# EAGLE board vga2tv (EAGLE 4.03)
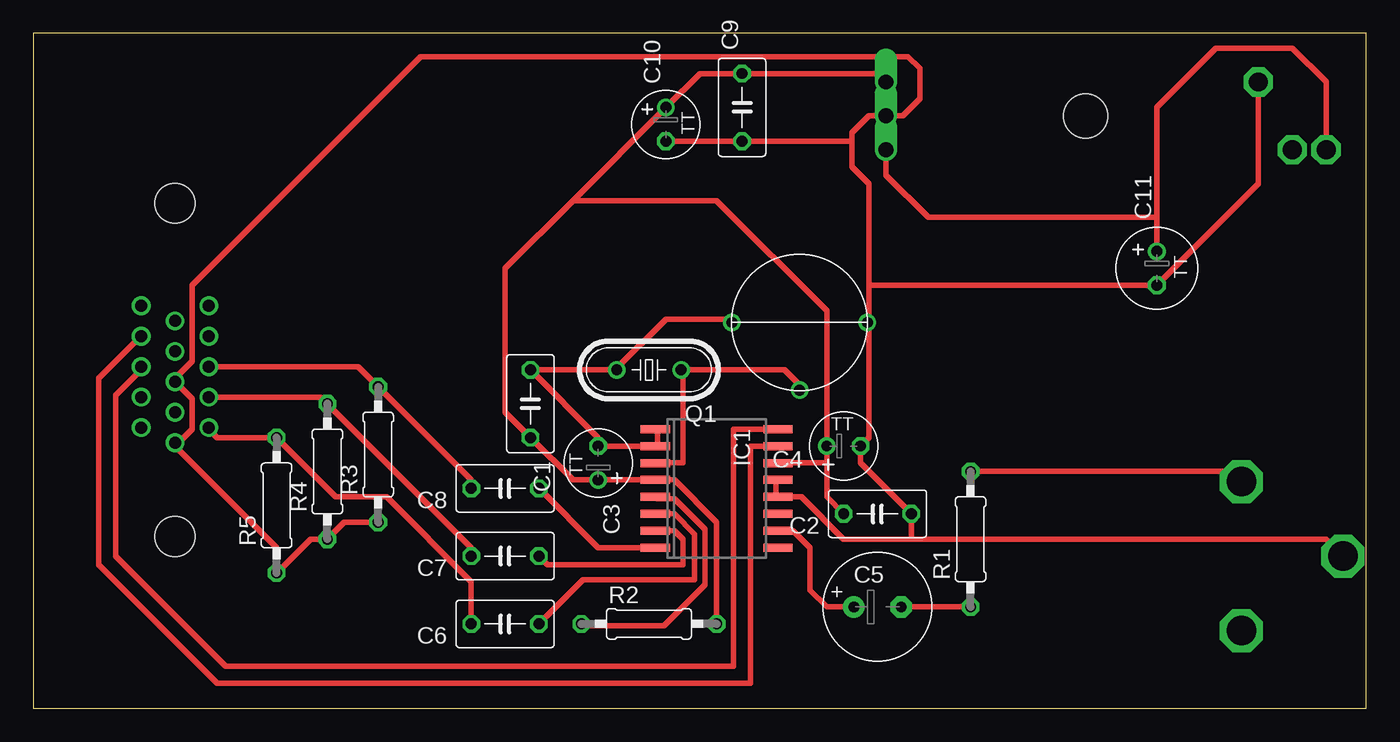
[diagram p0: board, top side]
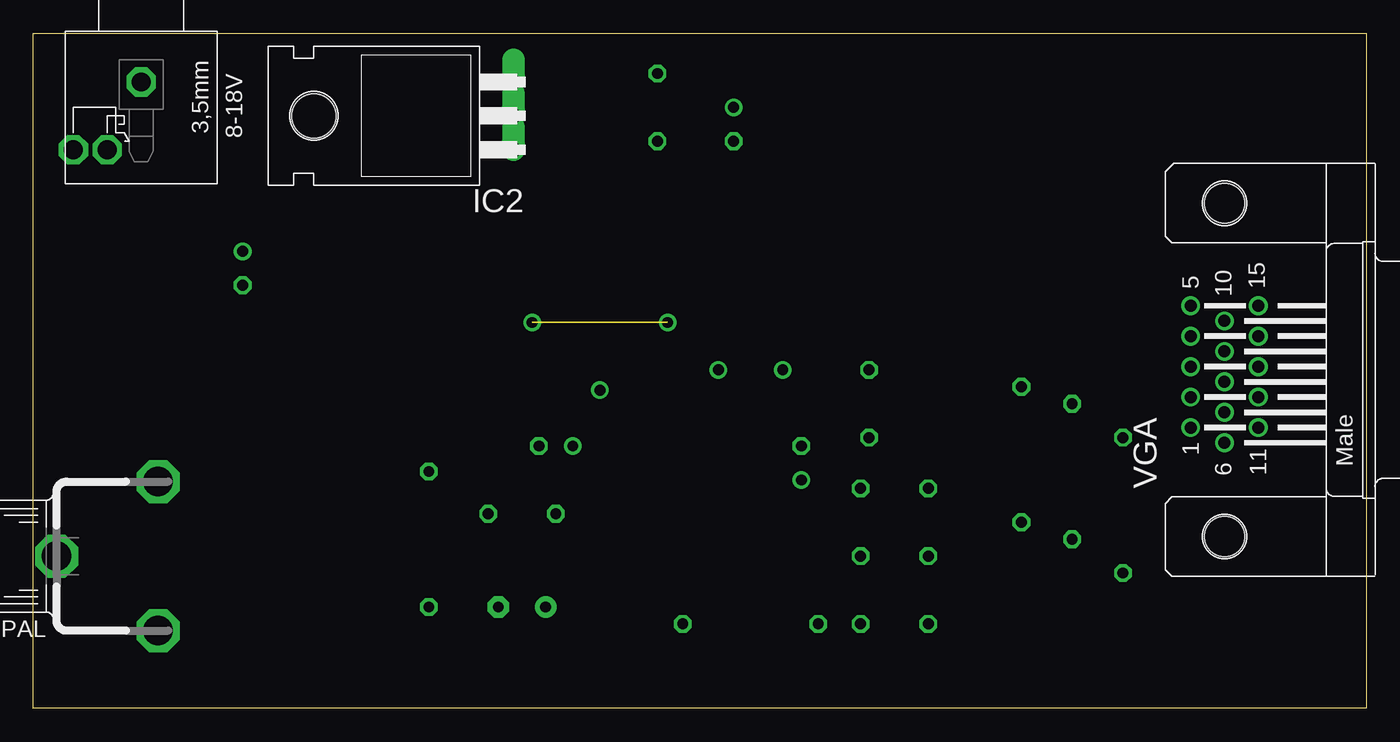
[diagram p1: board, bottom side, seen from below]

Size 100 x 50.63 mm. Coordinates in mm from the lower left corner, seen from the top.
Outline: 0,0 100,0 100,50.63 0,50.63 0,0
Copper layers used: Top
Net classes: 0 default: width 0.508 mm, drill 0.508 mm, clearance 0.381 mm

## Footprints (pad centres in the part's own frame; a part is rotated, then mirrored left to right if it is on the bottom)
PG203J = drill 1.422 pad 2.184 octagon: 1 -5.08,0; 2 0,-5.08; 3 0,-2.54
C050-035X075 = drill 0.813 octagon: 1 -2.54,0; 2 2.54,0
TT2D5 = drill 0.813 round: + 1.27,0 | drill 0.813 octagon: - -1.27,0
E3,5-8 = drill 0.813 pad 1.6 round: + -1.778,0 | drill 0.813 pad 1.6 octagon: - 1.778,0
TT2D6 = drill 0.813 round: + 1.27,0 | drill 0.813 octagon: - -1.27,0
SO16W = smd 0.6 x 2.2: 1 -4.445,-4.6; 2 -3.175,-4.6; 3 -1.905,-4.6; 4 -0.635,-4.6; 5 0.635,-4.6; 6 1.905,-4.6; 7 3.175,-4.6; 8 4.445,-4.6; 9 4.445,4.6; 10 3.175,4.6; 11 1.905,4.6; 12 0.635,4.6; 13 -0.635,4.6; 14 -1.905,4.6; 15 -3.175,4.6; 16 -4.445,4.6
TO220H = drill 1.118 offset: 1 -2.54,-10.16; 2 0,-10.16; 3 2.54,-10.16 | hole 3.302: 0,4.826
TOBU3 = drill 2.21 pad 3.226 octagon: 1 0,5.08; 2 5.588,-2.54; 3 -5.588,-2.54
HC49/S = drill 0.813 round: 1 -2.413,0; 2 2.413,0
0207/10 = drill 0.813 octagon: 1 -5.08,0; 2 5.08,0
VARCAP1 = drill 0.813 round: 1 0,5.08; 2 -5.08,0; 3 5.08,0
HDM15H = drill 0.9 round: 1 -4.329,2.54; 2 -2.043,2.54; 3 0.243,2.54; 4 2.529,2.54; 5 4.815,2.54; 6 -5.472,0; 7 -3.186,0; 8 -0.9,0; 9 1.386,0; 10 3.672,0; 11 -4.329,-2.54; 12 -2.043,-2.54; 13 0.243,-2.54; 14 2.529,-2.54; 15 4.815,-2.54 | hole 3: -12.5,0; 12.5,0

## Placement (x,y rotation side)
8-18V  PG203J""  [PG203J]  91.91,41.91 270 bottom
C1  0,1uF  [C050-035X075]  37.3,22.86 270 top
C2  0,1uF  [C050-035X075]  63.34,14.6 180 top
C3  10uF  [TT2D5]  42.38,18.41 270 top
C4  10uF  [TT2D5]  60.8,19.68 180 top
C5  220uF  [E3,5-8]  63.34,7.61 0 top
C6  0,1uF  [C050-035X075]  35.39,6.34 180 top
C7  0,1uF  [C050-035X075]  35.39,11.43 180 top
C8  0,1uF  [C050-035X075]  35.39,16.5 180 top
C9  100nF  [C050-035X075]  53.17,45.08 90 top
C10  10uF  [TT2D5]  47.46,43.81 90 top
C11  100uF  [TT2D6]  84.29,33.02 90 top
IC1  AD724JR  [SO16W]  51.27,16.5 270 top
IC2  7805T  [TO220H]  74.13,44.45 90 bottom
PAL  TOBU3""  [TOBU3]  93.18,11.43 90 bottom
Q1  4,43MHz  [HC49/S]  46.19,25.39 180 top
R1  75  [0207/10]  70.32,12.7 90 top
R2  10k  [0207/10]  46.19,6.34 0 top
R3  75  [0207/10]  25.87,19.05 90 top
R4  75  [0207/10]  22.06,17.78 90 top
R5  75  [0207/10]  18.25,15.24 90 top
VC1  10-30pF  [VARCAP1]  57.49,28.95 180 top
VGA  [HDM15H]  10.63,25.39 90 bottom

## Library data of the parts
8-18V IC1 PAL VC1 = vga2tv
C1-C11 R1-R5 = rcl
IC2 = linear
Q1 = crystal
VGA = con-subd

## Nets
+5V: C1.2 C2.2 C3.+ C4.+ C9.2 C10.+ IC1.4 IC1.14 IC2.3 R2.2
BIN: C8.1 IC1.8
BLU: C8.2 R3.2 VGA.3
CMPS: C5.+ IC1.10
FIN: IC1.3 Q1.1 VC1.1
GIN: C7.1 IC1.7
GND: 8-18V.1 C11.- R3.1 R4.1 R5.1 VGA.6 VGA.8
GRN: C7.2 R4.2 VGA.2
HSYNC: IC1.16 VGA.13
N$1: IC1.5 R2.1
N$5: C5.- R1.1
RED: C6.2 R5.2 VGA.1
RIN: C6.1 IC1.6
S$1: VC1.2 VC1.3
S$2: C2.1 C4.- IC1.12 IC1.13 PAL.1
S$3: C1.1 C3.- IC1.1 IC1.2 Q1.2
S$4: C9.1 C10.- IC2.2
TVOUT: PAL.2 R1.2
VCC: 8-18V.2 C11.+ IC2.1
VSYNC: IC1.15 VGA.14

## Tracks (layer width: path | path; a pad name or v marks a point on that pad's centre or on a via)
+5V
  Top 0.406: R2.2 51.27,13.96 48.09,17.14 IC1.4 C3.+ 40.48,17.14 C1.2 35.39,22.22 35.39,33.02 40.48,38.09 | 59.52,18.41 IC1.14 | IC2.3 63.34,47.62 C9.2 50,47.62 C10.+ 40.48,38.09 | 59.52,18.41 59.52,15.87 C2.2 | 59.52,18.41 C4.+ 59.52,29.84 51.27,38.09 40.48,38.09
BIN
  Top 0.406: IC1.8 42.38,12.06 C8.1
BLU
  Top 0.406: C8.2 32.85,17.14 R3.2 24.36,25.64 VGA.3
CMPS
  Top 0.406: IC1.10 56.98,13.33 58.25,12.06 58.25,8.88 59.52,7.61 C5.+
FIN
  Top 0.406: IC1.3 48.73,18.41 48.73,25.39 | 48.73,25.39 Q1.1 | VC1.1 57.49,24 57.62,24.12 56.35,25.39 48.73,25.39
GIN
  Top 0.406: IC1.7 48.09,13.33 48.73,12.7 48.73,10.79 38.57,10.79 C7.1
GND
  Top 0.406: 10.63,24.76 11.9,26.03 11.9,31.75 29.04,48.89 65.62,48.89 66.51,48 66.51,45.72 65.24,44.45 62.7,44.45 61.43,43.17 61.43,40.63 62.7,39.37 62.7,31.75 | VGA.8 11.9,23.23 11.9,20.95 10.63,19.68 | R3.1 23.33,13.96 R4.1 20.79,12.7 R5.1 18.25,12.06 10.63,19.68 | 10.63,19.68 VGA.6 | 8-18V.1 91.91,39.37 C11.- 62.7,31.75 | 62.7,31.75 62.7,20.32
  Top 0.508: VGA.8 10.63,24.76
GRN
  Top 0.406: C7.2 32.85,12.06 R4.2 21.56,23.35 VGA.2
HSYNC
  Top 0.406: IC1.16 52.54,20.95 52.54,3.17 14.44,3.17 6.18,11.43 6.18,23.49 8.09,25.39 VGA.13
N$1
  Top 0.406: IC1.5 46.8,15.74 48.09,15.74 50.38,13.46 50.38,9.27 47.33,6.22 41.24,6.22 R2.1
N$5
  Top 0.406: C5.- R1.1
RED
  Top 0.406: C6.2 32.85,9.52 26.5,15.87 22.7,15.87 R5.2 13.81,20.32 13.17,20.95 VGA.1
RIN
  Top 0.406: IC1.6 48.09,14.6 49.62,13.08 49.62,9.65 41.24,9.65 C6.1 37.81,6.22
S$1  (2 unrouted)
S$2
  Top 0.406: 62.7,20.32 C4.- 62.06,18.41 C2.1 65.88,12.7 | PAL.1 96.99,12.7 65.88,12.7 | IC1.13 55.71,17.14 55.71,16.02 IC1.12 | 65.88,12.7 60.8,12.7 57.62,15.87 IC1.12 | IC1.12 55.71,15.87
S$3
  Top 0.406: IC1.1 46.82,20.95 46.82,19.84 IC1.2 | IC1.2 46.82,19.68 | IC1.2 C3.- 42.38,20.32 C1.1 43.65,25.39 | 52.54,29.21 47.46,29.21 43.65,25.39 | 43.65,25.39 Q1.2
S$4
  Top 0.406: IC2.2 62.7,44.45 61.43,43.17 61.43,42.54 C9.1 C10.-
TVOUT
  Top 0.406: R1.2 90.64,17.78 PAL.2
VCC
  Top 0.406: IC2.1 63.97,40 67.14,36.83 84.29,36.83 | 84.29,36.83 C11.+ | 84.29,36.83 84.29,45.08 88.73,49.52 94.45,49.52 96.99,46.98 8-18V.2
VSYNC
  Top 0.406: IC1.15 53.81,19.68 53.81,1.9 13.81,1.9 4.92,10.79 4.92,24.76 VGA.14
